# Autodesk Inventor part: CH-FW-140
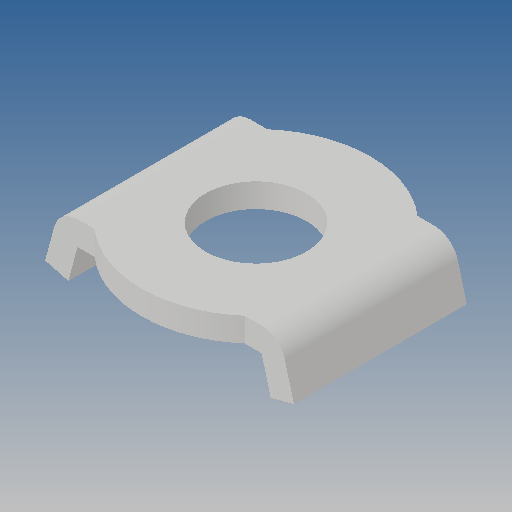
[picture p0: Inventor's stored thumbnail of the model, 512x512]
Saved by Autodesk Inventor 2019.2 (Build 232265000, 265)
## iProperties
Created: 2012-09
Part Number: CH-FW-140
Material: Ogólny
Document SubType Name: Modeling
Designer: CADENGINEERING4
Density: 1 g/cm^3
Appearance: Domyślna
Author: CADENGINEERING4
Revision Number: ÈÎºÎ
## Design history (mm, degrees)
feature "ÇÐ³ý-À­Éì1"
node "Bryła1"
